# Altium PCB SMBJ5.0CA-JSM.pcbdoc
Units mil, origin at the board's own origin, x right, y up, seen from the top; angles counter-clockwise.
Board outline 784.65 x 650 mil, 2 copper layers (Top Layer, Bottom Layer), stack 0 mil thick; 1 components, 0 nets, 2 pads, 0 vias.
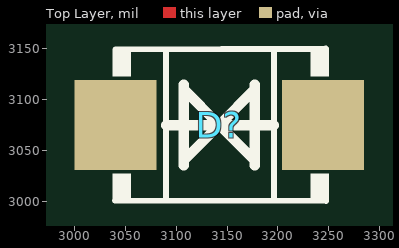
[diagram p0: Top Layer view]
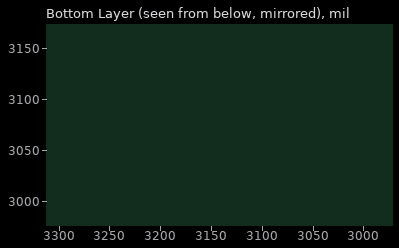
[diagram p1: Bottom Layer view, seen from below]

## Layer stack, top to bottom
Top Layer: signal copper (thickness not stored)
Bottom Layer: signal copper (thickness not stored)

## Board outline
3534.65,2750 2750,2750 2750,3400 3534.65,3400

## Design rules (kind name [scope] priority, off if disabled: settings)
PasteMaskExpansion "Paste Mask Expansion" [All] p1: expansion=0
SolderMaskExpansion "Solder Mask Expansion" [IsVia] p1: expansion=-1000 istentingtop=TRUE
SolderMaskExpansion "Solder Mask Expansion" [All] p2: expansion=2 istentingtop=FALSE

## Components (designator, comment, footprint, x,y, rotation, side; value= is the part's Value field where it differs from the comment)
D? "SMBJ5.0CA-JSM" SMB_L4.4-W3.6-LS5.3-BI 3142.32,3075 r0 top

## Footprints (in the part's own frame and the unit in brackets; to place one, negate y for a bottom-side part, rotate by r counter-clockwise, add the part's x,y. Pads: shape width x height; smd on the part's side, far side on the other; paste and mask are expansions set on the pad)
SMB_L4.4-W3.6-LS5.3-BI [mil]
  rect 80.61x88.23 smd: 1(-102.02,0) 2(102.02,0)
  silkscreen extent -105,-75 108,75

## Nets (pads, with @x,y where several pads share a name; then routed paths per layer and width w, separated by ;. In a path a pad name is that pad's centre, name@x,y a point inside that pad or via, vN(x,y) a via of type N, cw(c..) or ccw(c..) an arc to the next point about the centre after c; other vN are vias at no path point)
pads on no net: D?.1 D?.2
